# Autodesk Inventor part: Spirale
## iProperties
Created: 2005-04
Part Number: Spirale
Cost Center: 4840,4 g
Material: GD-Zn Al 4 Cu 1
Document SubType Name: Modeling
Designer: stampfer_r
Manufacturer: Standard
Standards Organization: Custom
Author: stampfer_r
SaveDate: 2005-04-21
SaveTime: 08:58
TotalMass: 4840,4 g
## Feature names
1. Extrusion1
2. Spirale1
